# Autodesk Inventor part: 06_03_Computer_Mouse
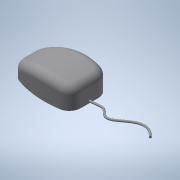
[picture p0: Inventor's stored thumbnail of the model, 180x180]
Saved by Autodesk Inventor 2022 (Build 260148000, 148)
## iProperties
Created: 2013-10
Part Number: 06_03_Computer_Mouse
Material: Generic
Document SubType Name: Modeling
Designer: John
Density: 1 g/cm^3
Appearance: Default
Author: John
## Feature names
1. Extrusion1
2. Extrusion2
3. Mirror1
4. Fillet1
5. Fillet2
6. Sweep1
## Parameters: d0 = 101.6 mm, d1 = 38.1 mm, d2 = 69.85 mm, d3 = 0, d4 = 69.85 mm, d5 = 0, d6 = 19.05 mm, d7 = 12.7 mm, d8 = -3.175 mm, d9 = 3.175 mm, d10 = 0, d11 = 0
